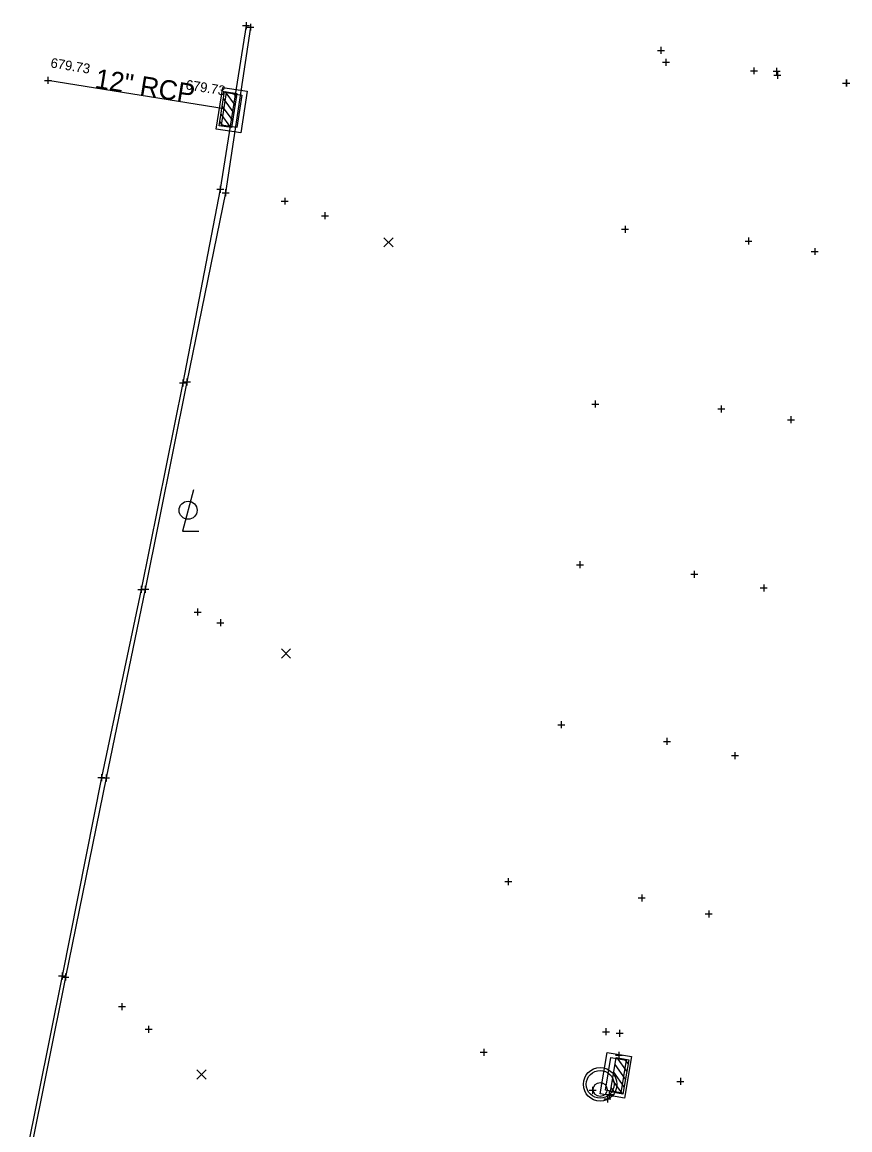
# Model space of a CAD drawing. Extents: x 2188719 to 2189819, y 654569 to 659504.
# Drawn here: x 2189585.2 to 2189704.4, y 657004.7 to 657164.3 of the extents above; entities that cross this region are included whole.
import ezdxf

# ---------------------------------------------------------------- set-up
doc = ezdxf.new("R2010")
doc.units = 0
for name, color, linetype in [('DR_X_Cells', 7, 'Continuous'), ('DR_X_Elev_Flow', 7, 'Continuous'), ('DR_X_Storm_Sewer', 7, 'Continuous'), ('DR_X_Text', 7, 'Continuous'), ('GK_Drainage_Nodes', 7, 'Continuous'), ('LT_X_Poles', 7, 'Continuous'), ('PV_X_Curb', 7, 'Continuous'), ('PV_X_EOP', 7, 'Continuous'), ('SC_Scratch1', 7, 'Continuous'), ('SV_X_Random_Point', 7, 'Continuous'), ('SV_X_Shot_Marker', 7, 'Continuous')]:
    doc.layers.add(name, color=color, linetype=linetype)

msp = doc.modelspace()

# ---------------------------------------------------------------- linework, layer by layer
at = {"layer": 'DR_X_Cells'}
for p, q in [((2189614.36, 657154.27), (2189615.83, 657152.26)), ((2189615.48, 657154.09), (2189616.01, 657153.38)), ((2189613.95, 657152.12), (2189615.49, 657150.03)), ((2189614.13, 657153.24), (2189615.66, 657151.15)), ((2189613.78, 657151), (2189615.19, 657149.08)), ((2189613.61, 657149.89), (2189614.07, 657149.25)), ((2189672.23, 657013.16), (2189670.84, 657015.1)), ((2189672.42, 657014.27), (2189671.96, 657014.91)), ((2189672.04, 657012.05), (2189670.54, 657014.15)), ((2189671.61, 657009.9), (2189670.16, 657011.92)), ((2189671.86, 657010.93), (2189670.35, 657013.04)), ((2189670.49, 657010.09), (2189669.98, 657010.81))]:
    msp.add_line(p, q, dxfattribs=at)
for points in [[(2189617.59, 657154.31), (2189616.65, 657148.3), (2189613.11, 657148.85), (2189614.04, 657154.86)], [(2189616.1, 657154), (2189615.33, 657149.06), (2189613.52, 657149.34), (2189614.29, 657154.28)], [(2189616.82, 657153.76), (2189616.09, 657149.06), (2189613.87, 657149.41), (2189614.6, 657154.1)], [(2189668.39, 657009.9), (2189669.39, 657015.89), (2189672.93, 657015.3), (2189671.92, 657009.3)], [(2189669.15, 657010.44), (2189669.94, 657015.13), (2189672.16, 657014.75), (2189671.37, 657010.07)], [(2189669.87, 657010.19), (2189670.7, 657015.13), (2189672.51, 657014.82), (2189671.68, 657009.89)]]:
    msp.add_lwpolyline(points, close=True, dxfattribs=at)
for centre, radius in [((2189668.4, 657011.29), 2.42), ((2189668.4, 657011.29), 2), ((2189668.4, 657010.54), 1)]:
    msp.add_circle(centre, radius, dxfattribs=at)
at = {"layer": 'DR_X_Elev_Flow'}
for p, q in [((2189588.38, 657155.87), (2189589.38, 657155.87)), ((2189588.88, 657156.37), (2189588.88, 657155.37)), ((2189588.88, 657155.87), (2189588.88, 657155.87))]:
    msp.add_line(p, q, dxfattribs=at)
at = {"layer": 'DR_X_Storm_Sewer'}
msp.add_line((2189614.24, 657151.76), (2189588.88, 657155.87), dxfattribs=at)
at = {"layer": 'GK_Drainage_Nodes'}
for p, q in [((2189615.71, 657153.93), (2189615.71, 657153.93)), ((2189613.58, 657151.86), (2189613.58, 657151.86)), ((2189614.24, 657151.76), (2189614.24, 657151.76)), ((2189615.35, 657151.58), (2189615.35, 657151.58)), ((2189615.72, 657151.53), (2189615.72, 657151.53)), ((2189615.72, 657151.53), (2189615.72, 657151.53)), ((2189616.46, 657151.41), (2189616.46, 657151.41)), ((2189617.12, 657151.31), (2189617.12, 657151.31)), ((2189614.98, 657149.24), (2189614.98, 657149.24)), ((2189671.05, 657014.94), (2189671.05, 657014.94)), ((2189668.4, 657013.29), (2189668.4, 657013.29)), ((2189668.89, 657012.89), (2189668.89, 657012.89)), ((2189669.55, 657012.78), (2189669.55, 657012.78)), ((2189670.29, 657012.66), (2189670.29, 657012.66)), ((2189670.29, 657012.66), (2189670.29, 657012.66)), ((2189670.66, 657012.6), (2189670.66, 657012.6)), ((2189671.77, 657012.41), (2189671.77, 657012.41)), ((2189672.42, 657012.3), (2189672.42, 657012.3)), ((2189668.4, 657011.29), (2189668.4, 657011.29)), ((2189668.4, 657011.29), (2189668.4, 657011.29)), ((2189668.4, 657010.54), (2189668.4, 657010.54)), ((2189670.26, 657010.26), (2189670.26, 657010.26)), ((2189668.4, 657009.29), (2189668.4, 657009.29))]:
    msp.add_line(p, q, dxfattribs=at)
msp.add_circle((2189668.4, 657011.29), 2, dxfattribs=at)
at = {"layer": 'LT_X_Poles'}
msp.add_lwpolyline([(2189609.84, 657096.92), (2189608.27, 657090.93), (2189610.63, 657090.93)], dxfattribs=at)
msp.add_circle((2189609.06, 657093.96), 1.3, dxfattribs=at)
at = {"layer": 'PV_X_Curb'}
for p, q in [((2189618.03, 657163.53), (2189614.46, 657139.68)), ((2189614.46, 657139.68), (2189608.89, 657112.43)), ((2189608.89, 657112.43), (2189602.89, 657082.59)), ((2189602.89, 657082.59), (2189597.25, 657055.41)), ((2189597.25, 657055.41), (2189591.41, 657026.74)), ((2189591.41, 657026.74), (2189585.66, 656998.21))]:
    msp.add_line(p, q, dxfattribs=at)
at = {"layer": 'PV_X_EOP'}
for p, q in [((2189617.4, 657163.75), (2189613.7, 657140.18)), ((2189613.7, 657140.18), (2189608.31, 657112.29)), ((2189608.31, 657112.29), (2189602.31, 657082.57)), ((2189602.31, 657082.57), (2189596.57, 657055.45)), ((2189596.57, 657055.45), (2189590.92, 657026.89)), ((2189590.92, 657026.89), (2189585.17, 656998.21))]:
    msp.add_line(p, q, dxfattribs=at)
at = {"layer": 'SV_X_Random_Point'}
for p, q in [((2189637.25, 657131.88), (2189638.58, 657133.21)), ((2189637.25, 657133.21), (2189638.58, 657131.88)), ((2189622.49, 657072.68), (2189623.82, 657074.01)), ((2189622.49, 657074.01), (2189623.82, 657072.68)), ((2189610.3, 657012.05), (2189611.64, 657013.39)), ((2189610.3, 657013.39), (2189611.64, 657012.05))]:
    msp.add_line(p, q, dxfattribs=at)
at = {"layer": 'SV_X_Shot_Marker'}
for p, q in [((2189616.9, 657163.75), (2189617.9, 657163.75)), ((2189617.4, 657164.25), (2189617.4, 657163.25)), ((2189617.4, 657163.75), (2189617.4, 657163.75)), ((2189617.53, 657163.53), (2189618.53, 657163.53)), ((2189618.03, 657164.03), (2189618.03, 657163.03)), ((2189618.03, 657163.53), (2189618.03, 657163.53)), ((2189676.64, 657160.19), (2189677.64, 657160.19)), ((2189677.14, 657160.69), (2189677.14, 657159.69)), ((2189677.14, 657160.19), (2189677.14, 657160.19)), ((2189677.36, 657158.48), (2189678.36, 657158.48)), ((2189677.86, 657158.98), (2189677.86, 657157.98)), ((2189677.86, 657158.48), (2189677.86, 657158.48)), ((2189690.05, 657157.24), (2189691.05, 657157.24)), ((2189690.55, 657157.74), (2189690.55, 657156.74)), ((2189690.55, 657157.24), (2189690.55, 657157.24)), ((2189693.31, 657157.17), (2189694.31, 657157.17)), ((2189693.81, 657157.67), (2189693.81, 657156.67)), ((2189693.81, 657157.17), (2189693.81, 657157.17)), ((2189693.93, 657157.11), (2189693.93, 657156.11)), ((2189693.43, 657156.61), (2189694.43, 657156.61)), ((2189693.93, 657156.61), (2189693.93, 657156.61)), ((2189703.3, 657155.48), (2189704.3, 657155.48)), ((2189703.35, 657155.48), (2189704.35, 657155.48)), ((2189703.8, 657155.98), (2189703.8, 657154.98)), ((2189703.8, 657155.48), (2189703.8, 657155.48)), ((2189703.85, 657155.98), (2189703.85, 657154.98)), ((2189703.85, 657155.48), (2189703.85, 657155.48)), ((2189613.2, 657140.18), (2189614.2, 657140.18)), ((2189613.7, 657140.68), (2189613.7, 657139.68)), ((2189613.7, 657140.18), (2189613.7, 657140.18)), ((2189613.96, 657139.68), (2189614.96, 657139.68)), ((2189614.46, 657140.18), (2189614.46, 657139.18)), ((2189614.46, 657139.68), (2189614.46, 657139.68)), ((2189622.47, 657138.47), (2189623.47, 657138.47)), ((2189622.47, 657138.47), (2189623.47, 657138.47)), ((2189622.97, 657138.97), (2189622.97, 657137.97)), ((2189622.97, 657138.97), (2189622.97, 657137.97)), ((2189622.97, 657138.47), (2189622.97, 657138.47)), ((2189622.97, 657138.47), (2189622.97, 657138.47)), ((2189628.26, 657136.37), (2189629.26, 657136.37)), ((2189628.76, 657136.87), (2189628.76, 657135.87)), ((2189628.76, 657136.37), (2189628.76, 657136.37)), ((2189671.99, 657134.93), (2189671.99, 657133.93)), ((2189671.49, 657134.43), (2189672.49, 657134.43)), ((2189671.99, 657134.43), (2189671.99, 657134.43)), ((2189689.76, 657133.23), (2189689.76, 657132.23)), ((2189689.26, 657132.73), (2189690.26, 657132.73)), ((2189689.76, 657132.73), (2189689.76, 657132.73)), ((2189699.3, 657131.72), (2189699.3, 657130.72)), ((2189698.8, 657131.22), (2189699.8, 657131.22)), ((2189699.3, 657131.22), (2189699.3, 657131.22)), ((2189607.81, 657112.29), (2189608.81, 657112.29)), ((2189608.31, 657112.79), (2189608.31, 657111.79)), ((2189608.31, 657112.29), (2189608.31, 657112.29)), ((2189608.39, 657112.43), (2189609.39, 657112.43)), ((2189608.89, 657112.93), (2189608.89, 657111.93)), ((2189608.89, 657112.43), (2189608.89, 657112.43)), ((2189667.19, 657109.25), (2189668.19, 657109.25)), ((2189667.69, 657109.75), (2189667.69, 657108.75)), ((2189667.69, 657109.25), (2189667.69, 657109.25)), ((2189685.83, 657109.05), (2189685.83, 657108.05)), ((2189685.33, 657108.55), (2189686.33, 657108.55)), ((2189685.83, 657108.55), (2189685.83, 657108.55)), ((2189695.87, 657107.5), (2189695.87, 657106.5)), ((2189695.37, 657107), (2189696.37, 657107)), ((2189695.87, 657107), (2189695.87, 657107)), ((2189665.48, 657086.61), (2189665.48, 657085.61)), ((2189664.98, 657086.11), (2189665.98, 657086.11)), ((2189665.48, 657086.11), (2189665.48, 657086.11)), ((2189681.94, 657085.24), (2189681.94, 657084.24)), ((2189681.44, 657084.74), (2189682.44, 657084.74)), ((2189681.94, 657084.74), (2189681.94, 657084.74)), ((2189601.81, 657082.57), (2189602.81, 657082.57)), ((2189602.31, 657083.07), (2189602.31, 657082.07)), ((2189602.31, 657082.57), (2189602.31, 657082.57)), ((2189602.39, 657082.59), (2189603.39, 657082.59)), ((2189602.89, 657083.09), (2189602.89, 657082.09)), ((2189602.89, 657082.59), (2189602.89, 657082.59)), ((2189691.45, 657082.77), (2189692.45, 657082.77)), ((2189691.95, 657083.27), (2189691.95, 657082.27)), ((2189691.95, 657082.77), (2189691.95, 657082.77)), ((2189609.93, 657079.29), (2189610.93, 657079.29)), ((2189609.93, 657079.29), (2189610.93, 657079.29)), ((2189610.43, 657079.79), (2189610.43, 657078.79)), ((2189610.43, 657079.79), (2189610.43, 657078.79)), ((2189610.43, 657079.29), (2189610.43, 657079.29)), ((2189610.43, 657079.29), (2189610.43, 657079.29)), ((2189613.21, 657077.76), (2189614.21, 657077.76)), ((2189613.71, 657078.26), (2189613.71, 657077.26)), ((2189613.71, 657077.76), (2189613.71, 657077.76)), ((2189662.29, 657063.07), (2189663.29, 657063.07)), ((2189662.79, 657063.57), (2189662.79, 657062.57)), ((2189662.79, 657063.07), (2189662.79, 657063.07)), ((2189678.02, 657061.17), (2189678.02, 657060.17)), ((2189677.52, 657060.67), (2189678.52, 657060.67)), ((2189678.02, 657060.67), (2189678.02, 657060.67)), ((2189687.3, 657058.63), (2189688.3, 657058.63)), ((2189687.8, 657059.13), (2189687.8, 657058.13)), ((2189687.8, 657058.63), (2189687.8, 657058.63)), ((2189596.07, 657055.45), (2189597.07, 657055.45)), ((2189596.57, 657055.95), (2189596.57, 657054.95)), ((2189596.57, 657055.45), (2189596.57, 657055.45)), ((2189596.75, 657055.41), (2189597.75, 657055.41)), ((2189597.25, 657055.91), (2189597.25, 657054.91)), ((2189597.25, 657055.41), (2189597.25, 657055.41)), ((2189654.66, 657040.49), (2189655.66, 657040.49)), ((2189655.16, 657040.99), (2189655.16, 657039.99)), ((2189655.16, 657040.49), (2189655.16, 657040.49)), ((2189673.88, 657038.13), (2189674.88, 657038.13)), ((2189674.38, 657038.63), (2189674.38, 657037.63)), ((2189674.38, 657038.13), (2189674.38, 657038.13)), ((2189683.54, 657035.82), (2189684.54, 657035.82)), ((2189684.04, 657036.32), (2189684.04, 657035.32)), ((2189684.04, 657035.82), (2189684.04, 657035.82)), ((2189590.42, 657026.89), (2189591.42, 657026.89)), ((2189590.91, 657026.74), (2189591.91, 657026.74)), ((2189590.92, 657027.39), (2189590.92, 657026.39)), ((2189590.92, 657026.89), (2189590.92, 657026.89)), ((2189591.41, 657027.24), (2189591.41, 657026.24)), ((2189591.41, 657026.74), (2189591.41, 657026.74)), ((2189599.54, 657022.97), (2189599.54, 657021.97)), ((2189599.54, 657022.97), (2189599.54, 657021.97)), ((2189599.04, 657022.47), (2189600.04, 657022.47)), ((2189599.04, 657022.47), (2189600.04, 657022.47)), ((2189599.54, 657022.47), (2189599.54, 657022.47)), ((2189599.54, 657022.47), (2189599.54, 657022.47)), ((2189603.37, 657019.71), (2189603.37, 657018.71)), ((2189602.87, 657019.21), (2189603.87, 657019.21)), ((2189603.37, 657019.21), (2189603.37, 657019.21)), ((2189668.72, 657018.86), (2189669.72, 657018.86)), ((2189669.22, 657019.36), (2189669.22, 657018.36)), ((2189669.22, 657018.86), (2189669.22, 657018.86)), ((2189670.69, 657018.63), (2189671.69, 657018.63)), ((2189671.19, 657019.13), (2189671.19, 657018.13)), ((2189671.19, 657018.63), (2189671.19, 657018.63)), ((2189651.14, 657015.9), (2189652.14, 657015.9)), ((2189651.64, 657016.4), (2189651.64, 657015.4)), ((2189651.64, 657015.9), (2189651.64, 657015.9)), ((2189670.6, 657015.48), (2189671.6, 657015.48)), ((2189671.1, 657015.98), (2189671.1, 657014.98)), ((2189671.1, 657015.48), (2189671.1, 657015.48)), ((2189679.46, 657011.71), (2189680.46, 657011.71)), ((2189679.96, 657012.21), (2189679.96, 657011.21)), ((2189679.96, 657011.71), (2189679.96, 657011.71)), ((2189666.8, 657010.42), (2189667.8, 657010.42)), ((2189667.3, 657010.92), (2189667.3, 657009.92)), ((2189667.3, 657010.42), (2189667.3, 657010.42)), ((2189669.71, 657010.31), (2189669.71, 657009.31)), ((2189668.94, 657009.18), (2189669.94, 657009.18)), ((2189669.21, 657009.81), (2189670.21, 657009.81)), ((2189669.44, 657009.68), (2189669.44, 657008.68)), ((2189669.44, 657009.18), (2189669.44, 657009.18)), ((2189669.71, 657009.81), (2189669.71, 657009.81))]:
    msp.add_line(p, q, dxfattribs=at)

# ---------------------------------------------------------------- texts
at = {"layer": 'DR_X_Text'}
msp.add_text('12" RCP', height=2.8, rotation=350.7892, dxfattribs=at).set_placement((2189595.52, 657154.81))
at = {"layer": 'SC_Scratch1'}
for p in [(2189589.18, 657157.74), (2189608.64, 657154.59)]:
    msp.add_text('679.73', height=1.4, rotation=350.7892, dxfattribs=at).set_placement(p)

doc.saveas('drawing.dxf')
